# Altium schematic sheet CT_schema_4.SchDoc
size 300 x 247 mm
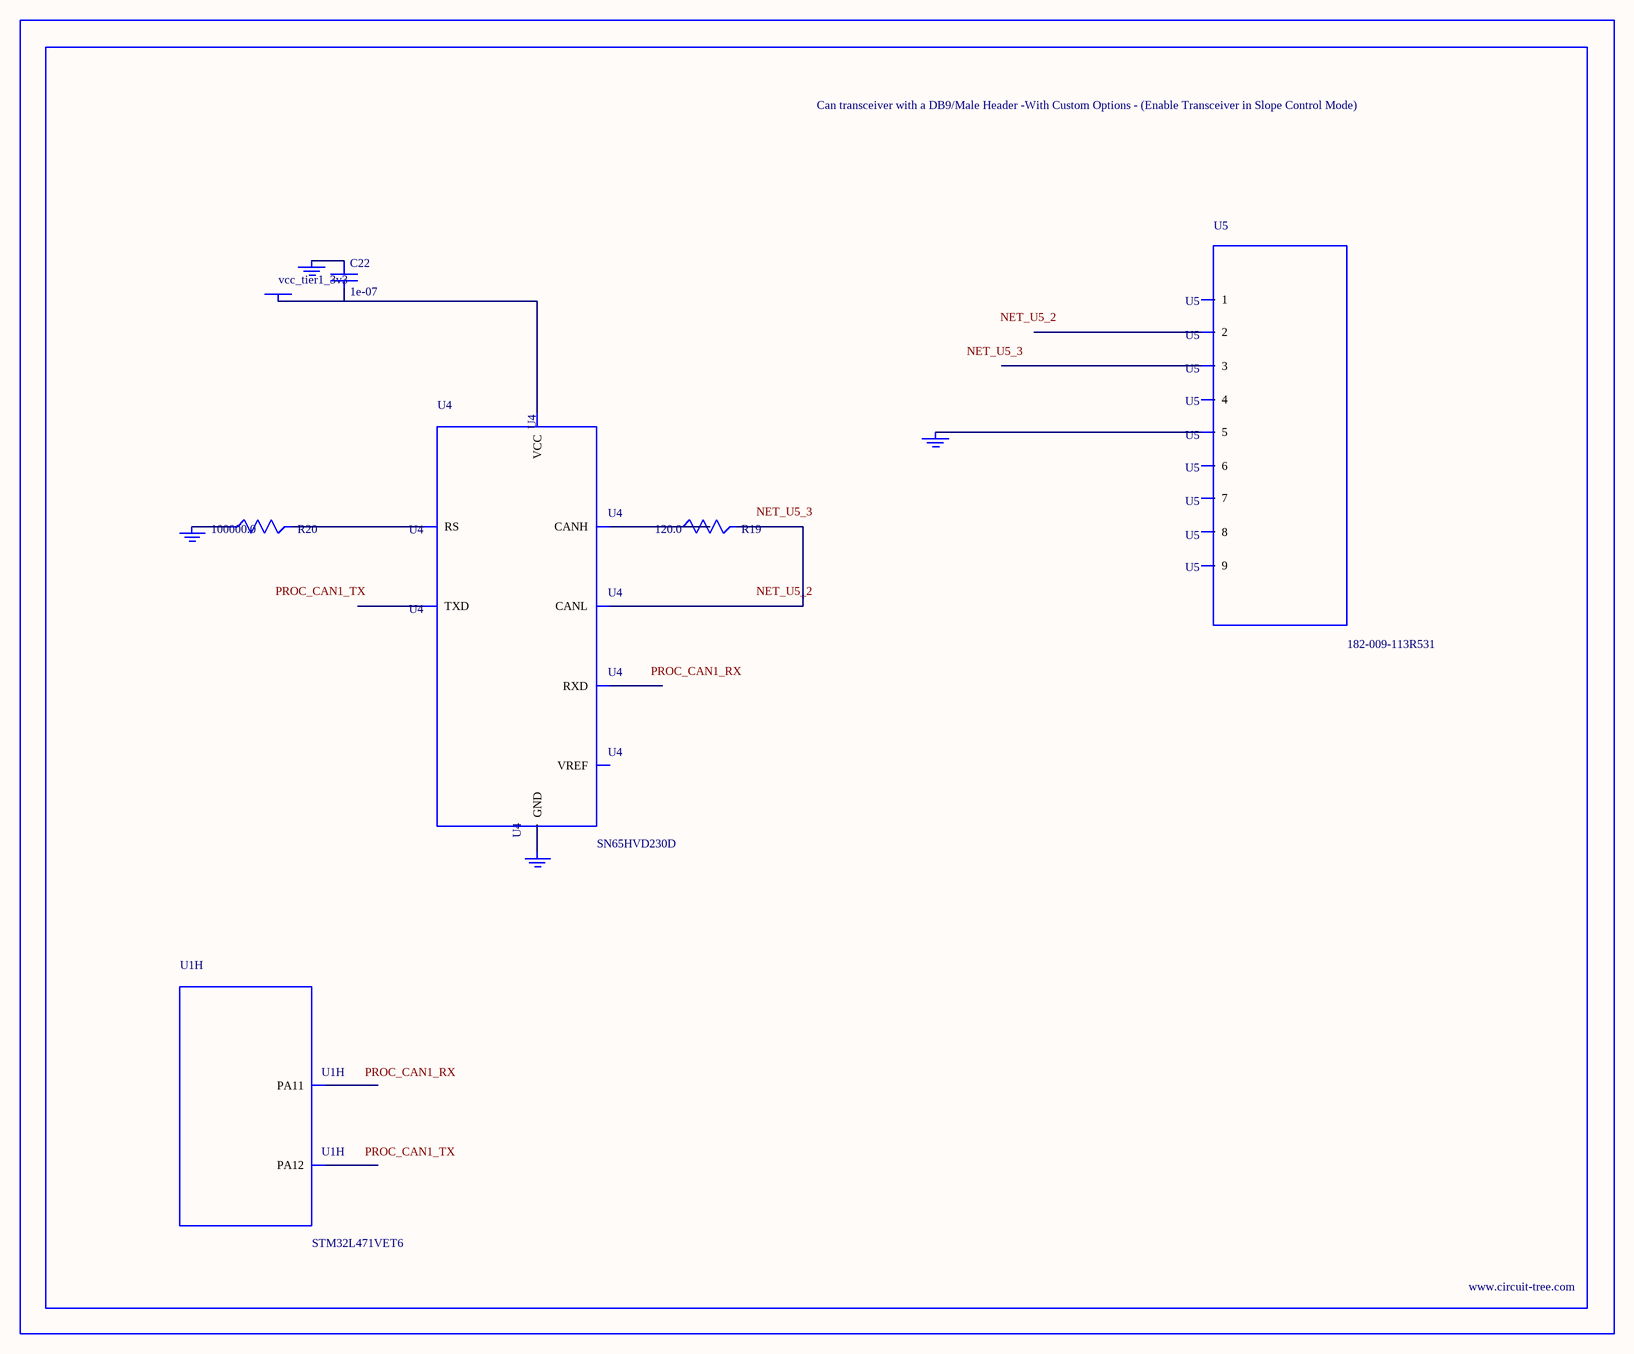
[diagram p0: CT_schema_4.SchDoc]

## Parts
BORDER3  (no value)
C22  1e-07  [C0402]
GND_INSTANCE_3_0  (no value)
GND_INSTANCE_3_1  (no value)
GND_INSTANCE_3_2  (no value)
GND_INSTANCE_3_3  (no value)
POWER_INSTANCE_3_0  vcc_tier1_3v3
R19  120.0  [R0603]
R20  100000.0  [R0603]
U1  STM32L471VET6  [LQFP100]  (part H of 11)
U4  SN65HVD230D  [SOIC-8]
U5  182-009-113R531  [182-009-MALE]

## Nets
NetC22_1: C22.1 GND_INSTANCE_3_0.0(GND)
NetC22_2: C22.2 POWER_INSTANCE_3_0.0(PWR) U4.3(VCC)
NetGND_INSTANCE_3_1_0: GND_INSTANCE_3_1.0(GND) R20.1
NetGND_INSTANCE_3_2_0: GND_INSTANCE_3_2.0(GND) U4.2(GND)
NetGND_INSTANCE_3_3_0: GND_INSTANCE_3_3.0(GND) U5.5
NetR19_1: R19.1 U4.7(CANH)
NetR19_2: R19.2 U4.6(CANL)
NetR20_2: R20.2 U4.8(RS)

Not connected (* = marked no-connect by the designer): U1 70(PA11) 71(PA12); U4 1(TXD) 4(RXD) 5(VREF); U5 1 2 3 4 6 7 8 9

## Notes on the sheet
- Labels drawn without touching a wire or pin: NET_U5_2, NET_U5_3, PROC_CAN1_RX, PROC_CAN1_TX

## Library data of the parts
BORDER3 = BORDER_PAGE3
C22 = C0402C104K3RACTU
GND_INSTANCE_3_0-GND_INSTANCE_3_3 = GND
POWER_INSTANCE_3_0 = PWR
R19 = RC0603JR-07120RL
R20 = RC0603JR-07100KL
